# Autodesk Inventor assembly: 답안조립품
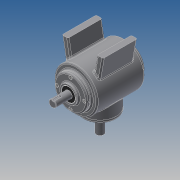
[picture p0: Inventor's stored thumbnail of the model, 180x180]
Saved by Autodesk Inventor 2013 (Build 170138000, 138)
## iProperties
Created: 2015-01
Part Number: 답안조립품
Document SubType Name: Assembly
Designer: kb54323
Author: kb54323
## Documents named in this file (15)
- C:\Users\kb54323\Desktop\450105v1036\답안조립품.iam
- C:\Users\kb54323\Desktop\450105v1036\본체.ipt
- C:\Users\kb54323\Desktop\450105v1036\메인 축.ipt
- 메인 축.ipt
- C:\Users\kb54323\Desktop\450105v1036\키 5x5.ipt
- C:\Users\kb54323\Desktop\450105v1036\메인 베벨기어.ipt
- C:\Users\kb54323\Desktop\450105v1036\베어링 6203.ipt
- C:\Users\kb54323\Desktop\450105v1036\커버.ipt
- C:\Users\kb54323\Desktop\450105v1036\서브 축.ipt
- 서브 축.ipt
- C:\Users\kb54323\Desktop\450105v1036\키 4x4.ipt
- C:\Users\kb54323\Desktop\450105v1036\서브 베벨기어.ipt
- C:\Users\kb54323\Desktop\450105v1036\오일실.ipt
- C:\Users\kb54323\Desktop\450105v1036\커버2.ipt
- C:\Users\kb54323\Desktop\450105v1036\M4.ipt
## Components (12 placed, 1 different names)
1. M4:1
2. M4:4
3. M4:5
4. M4:6
5. M4:2
6. M4:7
7. M4:8
8. M4:9
9. M4:3
10. M4:10
11. M4:11
12. M4:12
